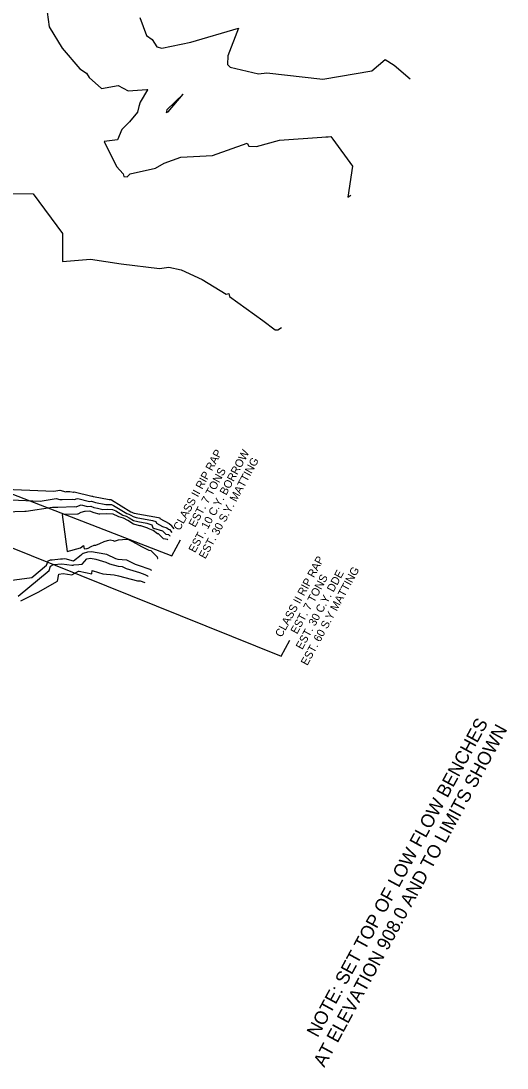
# Model space of a CAD drawing. Extents: x 1368651 to 1378602, y 762048 to 779328.
# Drawn here: x 1377329.5 to 1377511.8, y 762766.6 to 763159.3 of the extents above; entities that cross this region are included whole.
import ezdxf

# ---------------------------------------------------------------- set-up
doc = ezdxf.new("R2010")
doc.units = 0
for name, color, linetype in [('DTM Contours Major', 7, 'Continuous'), ('DTM Contours Minor', 7, 'Continuous'), ('Prop Erosion Rip Rap Class I Label', 7, 'Continuous')]:
    doc.layers.add(name, color=color, linetype=linetype)

msp = doc.modelspace()

# ---------------------------------------------------------------- linework, layer by layer
at = {"layer": 'DTM Contours Major'}
for points in [[(1377325.79, 762979.63), (1377336.64, 762979.2), (1377342.71, 762980.14), (1377344.03, 762979.81), (1377344.95, 762979.86), (1377348.76, 762979.95), (1377349.7, 762979.77), (1377350.19, 762980.03), (1377350.77, 762980.21), (1377355.24, 762979.12), (1377355.98, 762979.18), (1377356.69, 762978.9), (1377357.45, 762978.71), (1377361.36, 762977.93), (1377362.41, 762977.98), (1377363.49, 762977.94), (1377364.24, 762977.6), (1377369.23, 762974.58), (1377369.99, 762974.34), (1377370.7, 762973.97), (1377371.62, 762973.38), (1377372.67, 762973.1), (1377378.87, 762971.99), (1377380.06, 762971.62), (1377380.28, 762970.92), (1377382.59, 762969.67), (1377384.2, 762969.19), (1377384.78, 762968.63), (1377385.26, 762968.57), (1377386.02, 762967.47), (1377386.05, 762967.43)], [(1377328.47, 762943.51), (1377340.03, 762953.24), (1377340.6, 762954.82), (1377341.67, 762955.41), (1377344.88, 762955.71), (1377348.56, 762955.25), (1377349.09, 762955.16), (1377349.32, 762955.29), (1377351.2, 762955.4), (1377352.51, 762955.62), (1377354.14, 762957.62), (1377355.59, 762957.86), (1377357.58, 762957.5), (1377361.29, 762956.35), (1377362.66, 762955.72), (1377365.96, 762954.87), (1377367.46, 762954.73), (1377368.93, 762954), (1377373.9, 762952.44), (1377375.97, 762951.72), (1377376.99, 762951.17), (1377377.22, 762951)]]:
    msp.add_lwpolyline(points, dxfattribs=at)
at = {"layer": 'DTM Contours Minor'}
for points in [[(1377339, 763165.35), (1377340.02, 763157.09), (1377344.89, 763149.02), (1377351.63, 763141.27), (1377354.12, 763139.64), (1377355.07, 763138.01), (1377359.68, 763133.93), (1377365.94, 763135.04), (1377369.74, 763133.03), (1377376.67, 763133.58), (1377376.85, 763133.58), (1377377.05, 763133.52), (1377376.98, 763133.38), (1377374.23, 763128.83), (1377373.72, 763127.16), (1377373.19, 763125.02), (1377370.16, 763121.42), (1377367.37, 763118.54), (1377365.73, 763114.68), (1377360.64, 763113.99), (1377365.34, 763104.67), (1377367.84, 763101.97), (1377368.1, 763100.92), (1377369.29, 763100.81), (1377370.42, 763101.92), (1377380.01, 763104.11), (1377383.2, 763105.87), (1377389.43, 763108.23), (1377401.32, 763108.82), (1377414.3, 763113.39), (1377414.99, 763112.35), (1377417.81, 763112.18), (1377426.44, 763114.53), (1377442.36, 763115.67), (1377443.88, 763115.83), (1377444.7, 763115.74), (1377445.72, 763115.92), (1377446.48, 763114.87), (1377453.81, 763104.75), (1377452.12, 763093.2), (1377453.18, 763093.9)], [(1377374.11, 763160.57), (1377376.61, 763153.76), (1377378.73, 763152.29), (1377380.46, 763149.53), (1377382.36, 763149.09), (1377393.19, 763151.25), (1377411.05, 763156.6), (1377407.03, 763146.17), (1377407.01, 763142.96), (1377407.96, 763141.86), (1377418.59, 763139.47), (1377421.74, 763139.81), (1377442.71, 763137.39), (1377461.05, 763140.6), (1377466.09, 763144.81), (1377469.41, 763142.68), (1377475.5, 763137.52)], [(1377384.65, 763125.17), (1377390.29, 763131.8), (1377384.15, 763125.93), (1377384, 763124.88), (1377384.65, 763125.17)], [(1377326.41, 763094.53), (1377334.13, 763094.42), (1377345.03, 763079.54), (1377345.07, 763069.01), (1377355.54, 763069.92), (1377367.09, 763068.19), (1377381.43, 763066.49), (1377384.92, 763066.97), (1377389.6, 763065.89), (1377397.43, 763062.34), (1377406.43, 763056.75), (1377407.5, 763057.02), (1377407.7, 763055.95), (1377420.23, 763046.99), (1377424.8, 763043.47), (1377425.86, 763043.45), (1377427.23, 763044.35)], [(1377320.61, 762983.81), (1377341.85, 762982.96), (1377344.07, 762983.31), (1377346.33, 762982.73), (1377346.61, 762982.75), (1377347.77, 762982.78), (1377349.17, 762982.51), (1377349.31, 762982.59), (1377349.48, 762982.64), (1377356.09, 762981.03), (1377356.31, 762981.05), (1377356.52, 762980.96), (1377356.75, 762980.9), (1377362.53, 762979.76), (1377362.85, 762979.77), (1377363.17, 762979.76), (1377363.4, 762979.66), (1377370.76, 762975.2), (1377371.03, 762975.12), (1377371.27, 762974.99), (1377371.59, 762974.78), (1377371.96, 762974.69), (1377381.1, 762973.04), (1377381.55, 762972.91), (1377381.63, 762972.64), (1377385.12, 762970.76), (1377385.82, 762970.25), (1377385.87, 762970.11), (1377386.77, 762968.8), (1377386.78, 762968.79)], [(1377315.83, 762974.89), (1377330.97, 762975.46), (1377331.43, 762975.44), (1377341.35, 762976.98), (1377341.73, 762976.88), (1377343.28, 762976.97), (1377349.74, 762977.13), (1377350.24, 762977.04), (1377351.06, 762977.47), (1377352.05, 762977.78), (1377354.4, 762977.21), (1377355.65, 762977.3), (1377356.85, 762976.83), (1377358.14, 762976.51), (1377360.2, 762976.1), (1377361.98, 762976.18), (1377363.81, 762976.12), (1377365.08, 762975.55), (1377367.7, 762973.96), (1377368.95, 762973.57), (1377370.12, 762972.95), (1377371.64, 762971.98), (1377373.38, 762971.52), (1377376.64, 762970.93), (1377378.58, 762970.34), (1377378.94, 762969.19), (1377379.21, 762969.04), (1377382.62, 762968.04), (1377383.84, 762966.84), (1377384.87, 762966.71), (1377385.27, 762966.13), (1377385.32, 762966.08)], [(1377384.6, 762964.72), (1377384.51, 762964.8), (1377384.48, 762964.85), (1377382.91, 762965.05), (1377381.05, 762966.88), (1377380.65, 762966.99), (1377379.12, 762968.15), (1377377.14, 762968.92), (1377377.09, 762969.05), (1377374.4, 762969.88), (1377374.1, 762969.93), (1377371.67, 762970.58), (1377369.55, 762971.94), (1377367.91, 762972.79), (1377366.16, 762973.34), (1377365.91, 762973.49), (1377364.13, 762974.31), (1377361.54, 762974.39), (1377359.03, 762974.27), (1377358.84, 762974.31), (1377357.01, 762974.77), (1377355.32, 762975.43), (1377353.56, 762975.29), (1377353.34, 762975.35), (1377351.93, 762974.91), (1377350.77, 762974.3), (1377350.72, 762974.31), (1377344.93, 762974.16), (1377346.8, 762960.28), (1377351.81, 762961.75), (1377352.92, 762962.61), (1377353.26, 762961.31), (1377354.03, 762961.41), (1377354.35, 762961.5), (1377354.7, 762961.6), (1377355.79, 762962.23), (1377356.97, 762962.75), (1377357.6, 762962.64), (1377359.05, 762963.36), (1377360.69, 762964.12), (1377361.9, 762964.45), (1377362.96, 762964.64), (1377364.07, 762964.49), (1377364.59, 762964.14), (1377366.07, 762964.72), (1377369.04, 762964.91), (1377369.58, 762964.96), (1377371.04, 762964.19), (1377372.76, 762963.26), (1377374.74, 762962.18), (1377375.21, 762961.91), (1377377.5, 762960.82), (1377378.14, 762960.66), (1377380.58, 762958.26), (1377380.73, 762957.69), (1377380.79, 762957.64)], [(1377320.43, 762948.84), (1377333.61, 762950.58), (1377339.13, 762955.23), (1377339.72, 762956.85), (1377340.3, 762957.04), (1377340.56, 762957.14), (1377341.23, 762957.25), (1377344.38, 762957.51), (1377345.07, 762957.58), (1377345.79, 762957.68), (1377346.4, 762957.62), (1377348.6, 762956.94), (1377349.25, 762956.76), (1377352.13, 762959.07), (1377352.35, 762959.3), (1377352.6, 762959.47), (1377352.83, 762959.65), (1377352.99, 762959.67), (1377354.58, 762960.13), (1377355.96, 762960.36), (1377360.93, 762959.45), (1377361.52, 762959.27), (1377364.95, 762957.71), (1377365.84, 762957.47), (1377369.09, 762957.17), (1377372.28, 762955.59), (1377373.48, 762955.21), (1377377.78, 762953.7), (1377377.97, 762953.6), (1377378.43, 762953.26)], [(1377329.43, 762941.82), (1377335.89, 762945.04), (1377343.25, 762949.13), (1377343.7, 762951.84), (1377345.38, 762952.12), (1377348.62, 762951.58), (1377351.06, 762952.96), (1377351.28, 762952.97), (1377356.03, 762951.99), (1377356.25, 762953.18), (1377358.53, 762952.47), (1377360.21, 762951.88), (1377364.43, 762951.62), (1377366.08, 762951.13), (1377373.25, 762949.37), (1377374.25, 762949.26), (1377375.98, 762948.69)]]:
    msp.add_lwpolyline(points, dxfattribs=at)
at = {"layer": 'Prop Erosion Rip Rap Class I Label'}
for points in [[(1377257.14, 763008.52), (1377386.06, 762958.68), (1377389.32, 762964.73)], [(1377248.45, 762992.92), (1377427.12, 762921.08), (1377430.32, 762927.02)]]:
    msp.add_lwpolyline(points, dxfattribs=at)

# ---------------------------------------------------------------- texts
for s, height, p in [('CLASS II RIP RAP', 3, (1377389.05, 762967.93)), ('EST. 10 C.Y. BORROW', 3, (1377394.78, 762959.62)), ('EST. 30 S.Y. MATTING', 3, (1377398.65, 762957.32)), ('EST. 7 TONS', 3, (1377394.82, 762969.15)), ('CLASS II RIP RAP', 3, (1377427.26, 762927.91)), ('EST. 30 C.Y. DDE', 3, (1377435, 762923.3)), ('EST. 60 S.Y MATTING', 3, (1377436.88, 762917.32)), ('EST. 7 TONS', 3, (1377433.04, 762929.13)), ('NOTE: SET TOP OF LOW FLOW BENCHES', 5, (1377440.8, 762777.81)), (' AT ELEVATION 908.0 AND TO LIMITS SHOWN ', 5, (1377442.38, 762764.98))]:
    msp.add_text(s, height=height, rotation=61.5756, dxfattribs=at).set_placement(p)

doc.saveas('drawing.dxf')
